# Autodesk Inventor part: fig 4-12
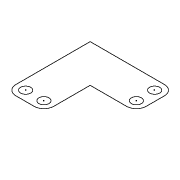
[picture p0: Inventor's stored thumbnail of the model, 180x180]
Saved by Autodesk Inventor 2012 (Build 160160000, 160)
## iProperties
Created: 2005-02
Part Number: fig 4-12
Document SubType Name: Modeling
Designer: CADCIM
Manufacturer: Standard
Standards Organization: Custom
Density: 1 g/cm^3
Material: Default
Author: CADCIM
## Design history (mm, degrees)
sketch "Sketch1"
  geometry: L1 (5.141, 24.979)-(-32.827, 24.979); L2 (-32.827, 24.979)-(-32.827, -12.989); L3 (-27.827, -17.989)-(-18.492, -17.989); L4 (-13.492, -12.989)-(-13.492, 5.644); L5 (-13.492, 5.644)-(5.141, 5.644); L6 (10.141, 10.644)-(10.141, 19.979); C1 r 2.58 at (-27.827, -12.989); C2 r 2.58 at (-18.492, -12.989); C3 r 2.58 at (5.141, 10.644); C4 r 2.58 at (5.141, 19.979); A1 r 5 centre (-27.827, -12.989) between (-32.827, -12.989) and (-27.827, -17.989); A2 r 5 centre (-18.492, -12.989) between (-18.492, -17.989) and (-13.492, -12.989); A3 r 5 centre (5.141, 10.644) between (5.141, 5.644) and (10.141, 10.644); A4 r 5 centre (5.141, 19.979) between (10.141, 19.979) and (5.141, 24.979)
  constraints: 12 end point, 8 centre point, 8 point on circle, 8 tangent, 4 equal radius, 4 parallel, 3 perpendicular, 2 coincident, 1 horizontal
